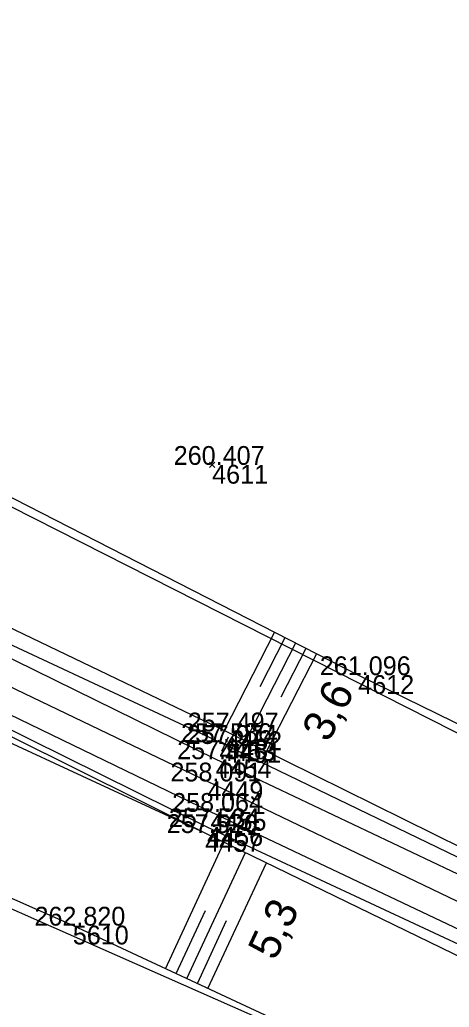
# Model space of a CAD drawing. Extents: x -809970 to -809480, y -1011362 to -1010672.
# Drawn here: x -809597.8 to -809570.4, y -1011259.5 to -1011196.5 of the extents above; entities that cross this region are included whole.
import ezdxf

# ---------------------------------------------------------------- set-up
doc = ezdxf.new("R2010")
doc.units = 0
for name, color, linetype in [('Vrstva 1', 7, 'Continuous'), ('Vrstva 4', 7, 'Continuous'), ('Vrstva 48', 7, 'Continuous'), ('Vrstva 49', 7, 'Continuous'), ('Vrstva 53', 7, 'Continuous'), ('Vrstva 60', 7, 'Continuous'), ('Vrstva 61', 7, 'Continuous'), ('Vrstva 7', 7, 'Continuous')]:
    doc.layers.add(name, color=color, linetype=linetype)

msp = doc.modelspace()

# ---------------------------------------------------------------- linework, layer by layer
at = {"layer": 'Vrstva 1'}
msp.add_lwpolyline([(-809516.045, -1011278.713), (-809523.512, -1011275.044), (-809540.806, -1011266.706), (-809563.528, -1011255.813), (-809585.837, -1011245.109), (-809604.949, -1011235.931), (-809607.598, -1011234.659), (-809621.677, -1011227.857)], dxfattribs=at)
at = {"layer": 'Vrstva 4'}
for points in [[(-809514.065, -1011276.667), (-809539.829, -1011264.256), (-809562.291, -1011253.601), (-809585.063, -1011242.594), (-809604.031, -1011233.738), (-809622.746, -1011224.339), (-809635.98, -1011217.776), (-809658.038, -1011205.96), (-809678.208, -1011194.437), (-809694.298, -1011183.842), (-809703.862, -1011176.66), (-809724.9, -1011159.776), (-809744.113, -1011141.604), (-809762.152, -1011122.163), (-809774.569, -1011106.334), (-809789.627, -1011085.975), (-809801.278, -1011067.08), (-809811.536, -1011048.018), (-809817.164, -1011036.691), (-809823.084, -1011022.979)], [(-809514.729, -1011277.553), (-809539.872, -1011265.306), (-809562.717, -1011254.424), (-809585.313, -1011243.688), (-809604.513, -1011234.263), (-809623.3, -1011225.163), (-809636.521, -1011218.939), (-809659.572, -1011206.8), (-809678.109, -1011195.782), (-809694.144, -1011185.083), (-809704.562, -1011177.6), (-809725.723, -1011160.529), (-809745.223, -1011142.426), (-809763.065, -1011123.227), (-809775.618, -1011107.424), (-809790.764, -1011086.703), (-809802.43, -1011068.088), (-809812.884, -1011048.592), (-809818.366, -1011037.45), (-809824.503, -1011023.859)], [(-809516.721, -1011279.856), (-809541.721, -1011267.845), (-809564.358, -1011257.132), (-809585.638, -1011247.052), (-809605.959, -1011237.208), (-809624.348, -1011228.403), (-809638.659, -1011221.376), (-809661.975, -1011208.931), (-809679.174, -1011198.728), (-809694.943, -1011188.715), (-809705.665, -1011180.871), (-809727.898, -1011162.906), (-809747.291, -1011144.847), (-809765.463, -1011125.116), (-809778.441, -1011109.547), (-809793.361, -1011088.57), (-809805.267, -1011069.597), (-809816.065, -1011050.215), (-809821.494, -1011039.157), (-809826.205, -1011028.819)], [(-809517.337, -1011281.17), (-809542.25, -1011268.906), (-809565.048, -1011257.741), (-809585.848, -1011248.029), (-809606.19, -1011237.964), (-809624.44, -1011229.457), (-809639.033, -1011221.782), (-809662.368, -1011209.594), (-809679.748, -1011199.238), (-809695.352, -1011189.158), (-809706.369, -1011181.628), (-809728.711, -1011163.52), (-809748.04, -1011145.819), (-809766.465, -1011126.184), (-809779.347, -1011110.294), (-809779.396, -1011110.263), (-809794.325, -1011089.309), (-809806.506, -1011070.337), (-809817.455, -1011050.768), (-809822.783, -1011039.81), (-809827.652, -1011029.26)]]:
    msp.add_lwpolyline(points, dxfattribs=at)
at = {"layer": 'Vrstva 48'}
for p, q in [((-809581.553, -1011235.587), (-809584.76, -1011241.855)), ((-809580.885, -1011235.929), (-809582.486, -1011239.058)), ((-809580.217, -1011236.271), (-809583.415, -1011242.519)), ((-809578.882, -1011236.954), (-809582.071, -1011243.184)), ((-809579.55, -1011236.613), (-809581.146, -1011239.732)), ((-809588.518, -1011257.067), (-809584.758, -1011248.997)), ((-809587.158, -1011257.701), (-809583.41, -1011249.654)), ((-809585.798, -1011258.334), (-809582.061, -1011250.311)), ((-809587.838, -1011257.384), (-809585.961, -1011253.355)), ((-809586.478, -1011258.017), (-809584.607, -1011254))]:
    msp.add_line(p, q, dxfattribs=at)
at = {"layer": 'Vrstva 49'}
for p, q in [((-809585.711, -1011224.717), (-809585.357, -1011225.071)), ((-809585.711, -1011225.071), (-809585.357, -1011224.717))]:
    msp.add_line(p, q, dxfattribs=at)
for points in [[(-809511.612, -1011271.228), (-809536.39, -1011258.331), (-809560.012, -1011246.273), (-809576.21, -1011238.322), (-809612.211, -1011219.896), (-809615.124, -1011217.125), (-809615.787, -1011215.734), (-809619.535, -1011223.553), (-809624.008, -1011221.315), (-809620.326, -1011213.386), (-809626.475, -1011211.634), (-809636.4, -1011208.191), (-809641.706, -1011205.475), (-809669.151, -1011190.804), (-809699.732, -1011169.398), (-809726.539, -1011146.854), (-809748.501, -1011124.908), (-809769.565, -1011100.553), (-809784.985, -1011078.508), (-809794.37, -1011063.913), (-809798.013, -1011059.085), (-809806.772, -1011045.247), (-809814.251, -1011034.457), (-809820.959, -1011021.87)], [(-809517.949, -1011282.175), (-809542.49, -1011269.58), (-809565.628, -1011258.317), (-809585.978, -1011248.403), (-809606.44, -1011238.24), (-809621.618, -1011231.052), (-809624.452, -1011230.402), (-809627.731, -1011228.864), (-809639.591, -1011222.812), (-809662.845, -1011211.141), (-809680.581, -1011200.68), (-809695.918, -1011190.366), (-809707.327, -1011182.303), (-809729.566, -1011164.319), (-809748.842, -1011146.407), (-809766.985, -1011126.934), (-809779.994, -1011110.776), (-809794.753, -1011089.666), (-809807.08, -1011070.596), (-809818.273, -1011051.222), (-809824.251, -1011040.285), (-809829.107, -1011030.235)], [(-809513.006, -1011276.135), (-809534.578, -1011266.087), (-809539.769, -1011263.863), (-809561.922, -1011253.155), (-809584.639, -1011241.913), (-809603.487, -1011232.879), (-809619.732, -1011225.036), (-809620.866, -1011223.988), (-809623.852, -1011222.566), (-809625.317, -1011222.489), (-809635.81, -1011217.558), (-809657.908, -1011205.698), (-809678.345, -1011193.87), (-809696.27, -1011181.606), (-809696.308, -1011181.589), (-809703.94, -1011175.693), (-809724.267, -1011159.214)], [(-809528.408, -1011284.669), (-809557.048, -1011271.632), (-809578.051, -1011261.943), (-809594.424, -1011254.316), (-809626.264, -1011240.209), (-809627.585, -1011240.006), (-809623.672, -1011231.942), (-809628.132, -1011229.779), (-809632.155, -1011237.957), (-809631.697, -1011238.186), (-809633.921, -1011240.113), (-809638.938, -1011239.661), (-809644.867, -1011236.23), (-809666.212, -1011224.996), (-809685.998, -1011209.539), (-809702.86, -1011197.497), (-809722.787, -1011182.74)], [(-809585.978, -1011248.403), (-809606.661, -1011238.842), (-809621.928, -1011231.807), (-809623.672, -1011231.942)]]:
    msp.add_lwpolyline(points, dxfattribs=at)
at = {"layer": 'Vrstva 53'}
for points in [[(-809817.83, -1011024.91), (-809805.06, -1011048.21), (-809777.13, -1011090.84), (-809773.31, -1011095.41), (-809752.3, -1011120.38), (-809722.41, -1011150.52), (-809685.06, -1011180.11), (-809638.61, -1011207.44), (-809624.45, -1011211.08), (-809620, -1011212.86), (-809615.56, -1011215.28), (-809614.76, -1011215.85), (-809598.39, -1011227.55), (-809488.36, -1011283.38)], [(-809479.96, -1011306.98), (-809541.53, -1011278.39), (-809624.88, -1011241.51), (-809627.72, -1011240.25), (-809632.39, -1011238.49), (-809632.72, -1011238.43), (-809644.97, -1011236.14), (-809685.42, -1011208.04), (-809719.22, -1011184.3), (-809751.99, -1011157.11), (-809779.01, -1011125.97), (-809796.54, -1011101.19), (-809810.89, -1011076.81), (-809836.26, -1011028.53)]]:
    msp.add_lwpolyline(points, dxfattribs=at)
at = {"layer": 'Vrstva 60'}
for p, q in [((-809585.534, -1011224.894), (-809585.534, -1011224.894)), ((-809576.21, -1011238.322), (-809576.21, -1011238.322)), ((-809584.639, -1011241.913), (-809584.639, -1011241.913)), ((-809585.063, -1011242.594), (-809585.063, -1011242.594)), ((-809584.702, -1011242.716), (-809584.702, -1011242.716)), ((-809585.313, -1011243.688), (-809585.313, -1011243.688)), ((-809585.837, -1011245.109), (-809585.837, -1011245.109)), ((-809585.638, -1011247.052), (-809585.638, -1011247.052)), ((-809585.978, -1011248.403), (-809585.978, -1011248.403)), ((-809585.848, -1011248.029), (-809585.848, -1011248.029)), ((-809594.424, -1011254.316), (-809594.424, -1011254.316))]:
    msp.add_line(p, q, dxfattribs=at)
at = {"layer": 'Vrstva 7'}
for p, q in [((-809584.251, -1011242.932), (-809585.153, -1011242.5)), ((-809584.918, -1011243.167), (-809584.486, -1011242.265))]:
    msp.add_line(p, q, dxfattribs=at)

# ---------------------------------------------------------------- texts
at = {"layer": 'Vrstva 48'}
for s, rotation, p in [('3,6', 62.89577, (-809578.108, -1011242.682)), ('5,3', 65.02258, (-809581.511, -1011256.613))]:
    msp.add_text(s, height=2, rotation=rotation, dxfattribs=at).set_placement(p)
at = {"layer": 'Vrstva 60'}
for s, p in [('4611', (-809585.534, -1011226.094)), ('4612', (-809576.21, -1011239.522)), ('4452', (-809584.639, -1011243.113)), ('4453', (-809585.063, -1011243.794)), ('4451', (-809584.702, -1011243.916)), ('4454', (-809585.313, -1011244.888)), ('4449', (-809585.837, -1011246.309)), ('4455', (-809585.638, -1011248.252)), ('4457', (-809585.978, -1011249.603)), ('4456', (-809585.848, -1011249.229)), ('5610', (-809594.424, -1011255.516))]:
    msp.add_text(s, height=1.2, dxfattribs=at).set_placement(p)
at = {"layer": 'Vrstva 61'}
for s, p in [('260.407', (-809587.986, -1011224.894)), ('261.096', (-809578.662, -1011238.322)), ('257.497', (-809587.091, -1011241.913)), ('257.586', (-809587.515, -1011242.594)), ('257.974', (-809587.153, -1011242.716)), ('257.948', (-809587.767, -1011243.688)), ('258.091', (-809588.194, -1011245.109)), ('258.064', (-809588.089, -1011247.052)), ('257.526', (-809588.43, -1011248.403)), ('257.534', (-809588.299, -1011248.029)), ('262.820', (-809596.875, -1011254.316))]:
    msp.add_text(s, height=1.2, dxfattribs=at).set_placement(p)

doc.saveas('drawing.dxf')
